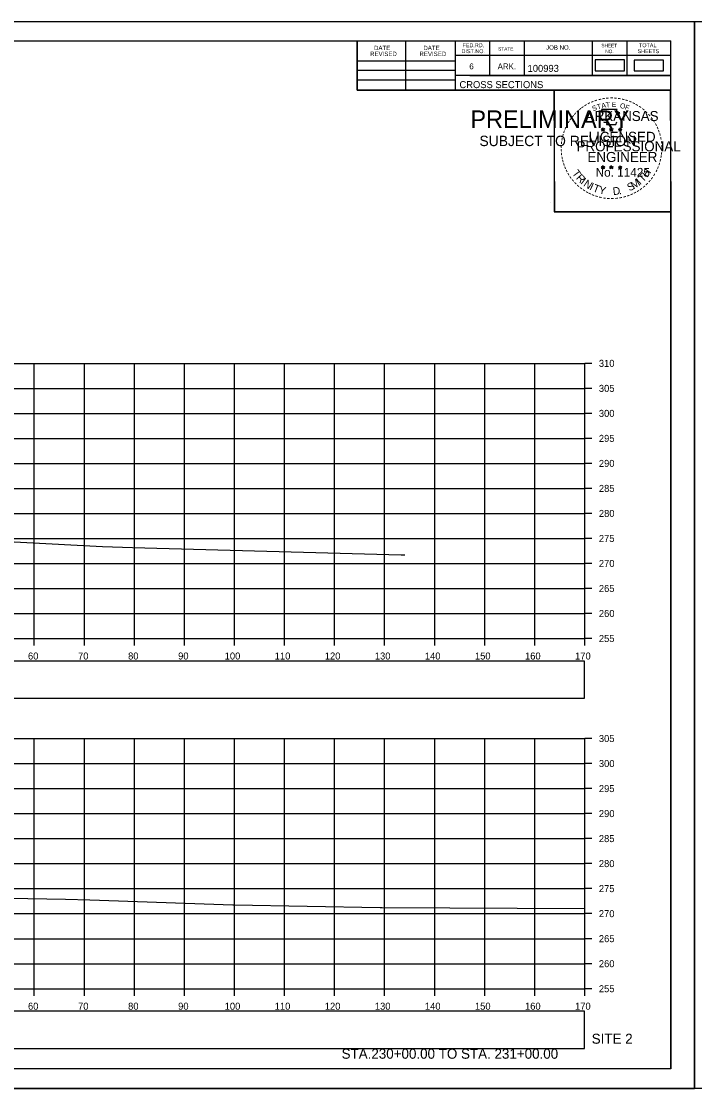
# Model space of a CAD drawing. Extents: x 4667 to 1632277, y -2100 to 724501.
# Drawn here: x 5834.6 to 5969.1, y 596.3 to 809.6 of the extents above; entities that cross this region are included whole.
import ezdxf

# ---------------------------------------------------------------- set-up
doc = ezdxf.new("R2010")
doc.units = 0
for name, color, linetype in [('Default', 7, 'Continuous'), ('R_Axis', 7, 'Continuous'), ('R_Axis Annot', 7, 'Continuous'), ('R_Border', 7, 'Continuous'), ('R_Border PE', 7, 'Continuous'), ('R_Border Prem', 7, 'Continuous'), ('R_Draft', 7, 'Continuous'), ('R_Exist Surface', 7, 'Continuous'), ('R_Grid', 7, 'Continuous'), ('R_No Plot', 7, 'Continuous'), ('R_Proposed CofA', 7, 'Continuous')]:
    doc.layers.add(name, color=color, linetype=linetype)

msp = doc.modelspace()

# ---------------------------------------------------------------- linework, layer by layer
at = {"layer": 'Default'}
for points in [[(5949.24, 799.74), (5955.07, 799.74), (5955.07, 801.92), (5949.24, 801.92)], [(5957.04, 799.71), (5962.87, 799.71), (5962.87, 801.89), (5957.04, 801.89)]]:
    msp.add_lwpolyline(points, close=True, dxfattribs=at)
at = {"layer": 'R_Axis'}
for p, q in [((5947.18, 686.27), (5947.18, 741.27)), ((5948.58, 741.27), (5947.18, 741.27)), ((5948.58, 736.27), (5947.18, 736.27)), ((5948.58, 731.27), (5947.18, 731.27)), ((5948.58, 726.27), (5947.18, 726.27)), ((5948.58, 721.27), (5947.18, 721.27)), ((5948.58, 716.27), (5947.18, 716.27)), ((5948.58, 711.27), (5947.18, 711.27)), ((5948.58, 706.27), (5947.18, 706.27)), ((5948.58, 701.27), (5947.18, 701.27)), ((5948.58, 696.27), (5947.18, 696.27)), ((5948.58, 691.27), (5947.18, 691.27)), ((5667.18, 686.27), (5947.18, 686.27)), ((5837.18, 684.87), (5837.18, 686.27)), ((5847.18, 684.87), (5847.18, 686.27)), ((5857.18, 684.87), (5857.18, 686.27)), ((5867.18, 684.87), (5867.18, 686.27)), ((5877.18, 684.87), (5877.18, 686.27)), ((5887.18, 684.87), (5887.18, 686.27)), ((5897.18, 684.87), (5897.18, 686.27)), ((5907.18, 684.87), (5907.18, 686.27)), ((5917.18, 684.87), (5917.18, 686.27)), ((5927.18, 684.87), (5927.18, 686.27)), ((5937.18, 684.87), (5937.18, 686.27)), ((5947.18, 684.87), (5947.18, 686.27)), ((5948.58, 686.27), (5947.18, 686.27)), ((5947.18, 616.27), (5947.18, 666.27)), ((5948.58, 666.27), (5947.18, 666.27)), ((5948.58, 661.27), (5947.18, 661.27)), ((5948.58, 656.27), (5947.18, 656.27)), ((5948.58, 651.27), (5947.18, 651.27)), ((5948.58, 646.27), (5947.18, 646.27)), ((5948.58, 641.27), (5947.18, 641.27)), ((5948.58, 636.27), (5947.18, 636.27)), ((5948.58, 631.27), (5947.18, 631.27)), ((5948.58, 626.27), (5947.18, 626.27)), ((5948.58, 621.27), (5947.18, 621.27)), ((5667.18, 616.27), (5947.18, 616.27)), ((5837.18, 614.87), (5837.18, 616.27)), ((5847.18, 614.87), (5847.18, 616.27)), ((5857.18, 614.87), (5857.18, 616.27)), ((5867.18, 614.87), (5867.18, 616.27)), ((5877.18, 614.87), (5877.18, 616.27)), ((5887.18, 614.87), (5887.18, 616.27)), ((5897.18, 614.87), (5897.18, 616.27)), ((5907.18, 614.87), (5907.18, 616.27)), ((5917.18, 614.87), (5917.18, 616.27)), ((5927.18, 614.87), (5927.18, 616.27)), ((5937.18, 614.87), (5937.18, 616.27)), ((5947.18, 614.87), (5947.18, 616.27)), ((5948.58, 616.27), (5947.18, 616.27))]:
    msp.add_line(p, q, dxfattribs=at)
at = {"layer": 'R_Border'}
for p, q in [((5648.18, 805.73), (5964.36, 805.73)), ((5901.72, 795.85), (5901.72, 805.73)), ((5911.4, 795.85), (5911.4, 805.73)), ((5921.26, 805.73), (5921.26, 795.85)), ((5928.1, 805.73), (5928.1, 798.79)), ((5935.04, 805.73), (5935.04, 798.79)), ((5948.62, 805.73), (5948.62, 798.79)), ((5955.56, 805.73), (5955.56, 798.79)), ((5964.36, 600.27), (5964.36, 805.73)), ((5964.36, 802.79), (5921.26, 802.79)), ((5964.36, 802.81), (5964.36, 802.81)), ((5901.72, 801.71), (5921.26, 801.71)), ((5901.72, 799.85), (5921.26, 799.85)), ((5901.72, 797.91), (5921.26, 797.91)), ((5964.36, 798.79), (5921.26, 798.79)), ((5924.22, 798.79), (5964.36, 798.79)), ((5964.36, 795.85), (5901.72, 795.85)), ((5964.36, 600.27), (5648.18, 600.27))]:
    msp.add_line(p, q, dxfattribs=at)
at = {"layer": 'R_Border PE'}
for p, q in [((5950.45, 788.11), (5950.8, 788)), ((5950.45, 788.11), (5950.7, 788.06)), ((5950.45, 788.11), (5950.69, 787.99)), ((5950.58, 787.7), (5950.8, 788)), ((5950.58, 787.7), (5950.71, 787.94)), ((5950.58, 787.7), (5950.8, 787.92)), ((5950.8, 788.36), (5950.76, 788.11)), ((5950.8, 788), (5950.8, 788.36)), ((5950.8, 788.36), (5950.85, 788.11)), ((5951.15, 788.11), (5950.8, 788)), ((5951.01, 787.7), (5950.8, 788)), ((5951.01, 787.7), (5950.8, 787.91)), ((5951.15, 788.11), (5950.86, 788.06)), ((5951.01, 787.7), (5950.87, 787.99)), ((5951.15, 788.11), (5950.94, 788.01)), ((5952.12, 788.11), (5952.47, 788)), ((5952.12, 788.11), (5952.37, 788.06)), ((5952.12, 788.11), (5952.36, 787.99)), ((5952.25, 787.7), (5952.47, 788)), ((5952.25, 787.7), (5952.38, 787.94)), ((5952.25, 787.7), (5952.47, 787.92)), ((5952.47, 788.36), (5952.43, 788.11)), ((5952.47, 788), (5952.47, 788.36)), ((5952.47, 788.36), (5952.52, 788.11)), ((5952.82, 788.11), (5952.47, 788)), ((5952.68, 787.7), (5952.47, 788)), ((5952.68, 787.7), (5952.47, 787.91)), ((5952.82, 788.11), (5952.53, 788.06)), ((5952.68, 787.7), (5952.54, 787.99)), ((5952.82, 788.11), (5952.61, 788.01)), ((5953.88, 788.1), (5954.23, 787.99)), ((5953.88, 788.1), (5954.14, 788.05)), ((5953.88, 788.1), (5954.12, 787.97)), ((5954.02, 787.69), (5954.23, 787.99)), ((5954.02, 787.69), (5954.14, 787.93)), ((5954.02, 787.69), (5954.23, 787.91)), ((5954.23, 788.35), (5954.19, 788.1)), ((5954.23, 787.99), (5954.23, 788.35)), ((5954.23, 788.35), (5954.28, 788.1)), ((5954.58, 788.1), (5954.23, 787.99)), ((5954.45, 787.69), (5954.23, 787.99)), ((5954.45, 787.69), (5954.23, 787.9)), ((5954.58, 788.1), (5954.29, 788.05)), ((5954.45, 787.69), (5954.31, 787.98)), ((5954.58, 788.1), (5954.38, 787.99)), ((5950.45, 780.54), (5950.79, 780.42)), ((5950.45, 780.54), (5950.7, 780.49)), ((5950.45, 780.54), (5950.68, 780.41)), ((5950.58, 780.13), (5950.79, 780.42)), ((5950.58, 780.13), (5950.7, 780.37)), ((5950.58, 780.13), (5950.79, 780.34)), ((5950.79, 780.79), (5950.75, 780.54)), ((5950.79, 780.42), (5950.79, 780.79)), ((5950.79, 780.79), (5950.84, 780.54)), ((5951.14, 780.54), (5950.79, 780.42)), ((5951.01, 780.13), (5950.79, 780.42)), ((5951.01, 780.13), (5950.79, 780.34)), ((5951.14, 780.54), (5950.86, 780.49)), ((5951.01, 780.13), (5950.87, 780.42)), ((5951.14, 780.54), (5950.94, 780.43)), ((5952.11, 780.54), (5952.46, 780.42)), ((5952.11, 780.54), (5952.37, 780.49)), ((5952.11, 780.54), (5952.35, 780.41)), ((5952.25, 780.13), (5952.46, 780.42)), ((5952.25, 780.13), (5952.37, 780.37)), ((5952.25, 780.13), (5952.46, 780.34)), ((5952.46, 780.79), (5952.42, 780.54)), ((5952.46, 780.42), (5952.46, 780.79)), ((5952.46, 780.79), (5952.51, 780.54)), ((5952.81, 780.54), (5952.46, 780.42)), ((5952.68, 780.13), (5952.46, 780.42)), ((5952.68, 780.13), (5952.46, 780.34)), ((5952.81, 780.54), (5952.52, 780.49)), ((5952.68, 780.13), (5952.54, 780.42)), ((5952.81, 780.54), (5952.61, 780.43)), ((5953.88, 780.53), (5954.23, 780.41)), ((5953.88, 780.53), (5954.13, 780.48)), ((5953.88, 780.53), (5954.12, 780.4)), ((5954.01, 780.12), (5954.23, 780.41)), ((5954.01, 780.12), (5954.14, 780.36)), ((5954.01, 780.12), (5954.23, 780.33)), ((5954.23, 780.78), (5954.19, 780.53)), ((5954.23, 780.41), (5954.23, 780.78)), ((5954.23, 780.78), (5954.28, 780.53)), ((5954.58, 780.53), (5954.23, 780.41)), ((5954.44, 780.12), (5954.23, 780.41)), ((5954.44, 780.12), (5954.23, 780.33)), ((5954.58, 780.53), (5954.29, 780.48)), ((5954.44, 780.12), (5954.31, 780.41)), ((5954.58, 780.53), (5954.37, 780.42))]:
    msp.add_line(p, q, dxfattribs=at)
for points in [[(5950.49, 791.99), (5950.76, 791.16)], [(5954, 791.06), (5954.14, 791.35), (5953.46, 791.32), (5953.61, 791.99), (5950.49, 791.99)], [(5950.98, 789.56), (5950.98, 789.48), (5951.55, 789.46), (5951.49, 788.98), (5953.36, 788.98), (5953.56, 789.52)], [(5950.8, 788.36), (5951.01, 787.7), (5950.45, 788.11), (5951.15, 788.11), (5950.58, 787.7), (5950.8, 788.36)], [(5952.47, 788.36), (5952.68, 787.7), (5952.12, 788.11), (5952.82, 788.11), (5952.25, 787.7), (5952.47, 788.36)], [(5954.23, 788.35), (5954.45, 787.69), (5953.88, 788.1), (5954.58, 788.1), (5954.02, 787.69), (5954.23, 788.35)], [(5950.79, 780.79), (5951.01, 780.13), (5950.45, 780.54), (5951.14, 780.54), (5950.58, 780.13), (5950.79, 780.79)], [(5952.46, 780.79), (5952.68, 780.13), (5952.11, 780.54), (5952.81, 780.54), (5952.25, 780.13), (5952.46, 780.79)], [(5954.23, 780.78), (5954.44, 780.12), (5953.88, 780.53), (5954.58, 780.53), (5954.01, 780.12), (5954.23, 780.78)]]:
    msp.add_lwpolyline(points, dxfattribs=at)
for centre, radius in [((5950.8, 788), 0.172), ((5950.8, 788), 0.145), ((5950.8, 788), 0.116), ((5950.8, 788), 0.0991), ((5950.8, 788), 0.0747), ((5950.8, 788), 0.0495), ((5950.8, 788), 0.0296), ((5952.47, 788), 0.172), ((5952.47, 788), 0.145), ((5952.47, 788), 0.116), ((5952.47, 788), 0.0991), ((5952.47, 788), 0.0747), ((5952.47, 788), 0.0495), ((5952.47, 788), 0.0296), ((5954.23, 787.98), 0.172), ((5954.23, 787.98), 0.145), ((5954.23, 787.98), 0.116), ((5954.23, 787.98), 0.0991), ((5954.23, 787.98), 0.0747), ((5954.23, 787.98), 0.0495), ((5954.23, 787.98), 0.0296), ((5950.79, 780.42), 0.172), ((5950.79, 780.42), 0.145), ((5950.79, 780.42), 0.116), ((5950.79, 780.42), 0.0991), ((5950.79, 780.42), 0.0747), ((5950.79, 780.42), 0.0495), ((5950.79, 780.42), 0.0296), ((5952.46, 780.42), 0.172), ((5952.46, 780.42), 0.145), ((5952.46, 780.42), 0.116), ((5952.46, 780.42), 0.0991), ((5952.46, 780.42), 0.0747), ((5952.46, 780.42), 0.0495), ((5952.46, 780.42), 0.0296), ((5954.23, 780.41), 0.172), ((5954.23, 780.41), 0.145), ((5954.23, 780.41), 0.116), ((5954.23, 780.41), 0.0991), ((5954.23, 780.41), 0.0747), ((5954.23, 780.41), 0.0495), ((5954.23, 780.41), 0.0296)]:
    msp.add_circle(centre, radius, dxfattribs=at)
at = {"layer": 'R_Exist Surface'}
for points in [[(5816.73, 706.49), (5850.8, 704.64), (5856.81, 704.46), (5910.49, 702.99), (5911.23, 702.96)], [(5817.13, 634.66), (5843.4, 634.16), (5848.28, 634.06), (5876.85, 633.04), (5877.11, 633.03), (5906.26, 632.5), (5906.67, 632.49), (5947.18, 632.31)]]:
    msp.add_lwpolyline(points, dxfattribs=at)
at = {"layer": 'R_Grid'}
for p, q in [((5667.18, 741.27), (5947.18, 741.27)), ((5837.18, 686.27), (5837.18, 741.27)), ((5847.18, 686.27), (5847.18, 741.27)), ((5857.18, 686.27), (5857.18, 741.27)), ((5867.18, 686.27), (5867.18, 741.27)), ((5877.18, 686.27), (5877.18, 741.27)), ((5887.18, 686.27), (5887.18, 741.27)), ((5897.18, 686.27), (5897.18, 741.27)), ((5907.18, 686.27), (5907.18, 741.27)), ((5917.18, 686.27), (5917.18, 741.27)), ((5927.18, 686.27), (5927.18, 741.27)), ((5937.18, 686.27), (5937.18, 741.27)), ((5947.18, 686.27), (5947.18, 741.27)), ((5667.18, 736.27), (5947.18, 736.27)), ((5667.18, 731.27), (5947.18, 731.27)), ((5667.18, 726.27), (5947.18, 726.27)), ((5667.18, 721.27), (5947.18, 721.27)), ((5667.18, 716.27), (5947.18, 716.27)), ((5667.18, 711.27), (5947.18, 711.27)), ((5667.18, 706.27), (5947.18, 706.27)), ((5667.18, 701.27), (5947.18, 701.27)), ((5667.18, 696.27), (5947.18, 696.27)), ((5667.18, 691.27), (5947.18, 691.27)), ((5667.18, 686.27), (5947.18, 686.27)), ((5667.18, 666.27), (5947.18, 666.27)), ((5837.18, 616.27), (5837.18, 666.27)), ((5847.18, 616.27), (5847.18, 666.27)), ((5857.18, 616.27), (5857.18, 666.27)), ((5867.18, 616.27), (5867.18, 666.27)), ((5877.18, 616.27), (5877.18, 666.27)), ((5887.18, 616.27), (5887.18, 666.27)), ((5897.18, 616.27), (5897.18, 666.27)), ((5907.18, 616.27), (5907.18, 666.27)), ((5917.18, 616.27), (5917.18, 666.27)), ((5927.18, 616.27), (5927.18, 666.27)), ((5937.18, 616.27), (5937.18, 666.27)), ((5947.18, 616.27), (5947.18, 666.27)), ((5667.18, 661.27), (5947.18, 661.27)), ((5667.18, 656.27), (5947.18, 656.27)), ((5667.18, 651.27), (5947.18, 651.27)), ((5667.18, 646.27), (5947.18, 646.27)), ((5667.18, 641.27), (5947.18, 641.27)), ((5667.18, 636.27), (5947.18, 636.27)), ((5667.18, 631.27), (5947.18, 631.27)), ((5667.18, 626.27), (5947.18, 626.27)), ((5667.18, 621.27), (5947.18, 621.27)), ((5667.18, 616.27), (5947.18, 616.27))]:
    msp.add_line(p, q, dxfattribs=at)
at = {"layer": 'R_No Plot'}
for p, q in [((5635.78, 809.63), (5969.12, 809.63)), ((5940.4, 773.4), (5940.4, 773.4)), ((5635.78, 596.29), (5969.12, 596.29))]:
    msp.add_line(p, q, dxfattribs=at)
for points in [[(5635.78, 809.63), (5969.12, 809.63), (5969.12, 596.29), (5635.78, 596.29)], [(5969.12, 809.63), (6302.46, 809.63), (6302.46, 596.29), (5969.12, 596.29)], [(5882.1, 805.73), (5901.72, 805.73), (5901.72, 795.85), (5917.84, 795.85), (5941.04, 795.85), (5941.04, 771.52), (5964.36, 771.52), (5964.36, 600.27), (5648.18, 600.27), (5648.18, 805.73)], [(5941.04, 795.85), (5964.24, 795.85), (5964.36, 771.52), (5941.16, 771.52)]]:
    msp.add_lwpolyline(points, close=True, dxfattribs=at)
at = {"layer": 'R_Proposed CofA'}
for points in [[(5667.23, 674.33), (5947.13, 674.33), (5947.13, 681.75), (5667.23, 681.75)], [(5667.23, 604.33), (5947.13, 604.33), (5947.13, 611.75), (5667.23, 611.75)]]:
    msp.add_lwpolyline(points, close=True, dxfattribs=at)

# ---------------------------------------------------------------- texts
at = {"layer": 'R_Axis Annot'}
for s, p in [('310', (5949.98, 740.57)), ('305', (5949.98, 735.57)), ('300', (5949.98, 730.57)), ('295', (5949.98, 725.57)), ('290', (5949.98, 720.57)), ('285', (5949.98, 715.57)), ('280', (5949.98, 710.57)), ('275', (5949.98, 705.57)), ('270', (5949.98, 700.57)), ('265', (5949.98, 695.57)), ('260', (5949.98, 690.57)), ('255', (5949.98, 685.57)), ('60', (5835.92, 682.07)), ('70', (5845.92, 682.07)), ('80', (5855.92, 682.07)), ('90', (5865.92, 682.07)), ('100', (5875.22, 682.07)), ('110', (5885.22, 682.07)), ('120', (5895.22, 682.07)), ('130', (5905.22, 682.07)), ('140', (5915.22, 682.07)), ('150', (5925.22, 682.07)), ('160', (5935.22, 682.07)), ('170', (5945.22, 682.07)), ('305', (5949.98, 665.57)), ('300', (5949.98, 660.57)), ('295', (5949.98, 655.57)), ('290', (5949.98, 650.57)), ('285', (5949.98, 645.57)), ('280', (5949.98, 640.57)), ('275', (5949.98, 635.57)), ('270', (5949.98, 630.57)), ('265', (5949.98, 625.57)), ('260', (5949.98, 620.57)), ('255', (5949.98, 615.57)), ('60', (5835.92, 612.07)), ('70', (5845.92, 612.07)), ('80', (5855.92, 612.07)), ('90', (5865.92, 612.07)), ('100', (5875.22, 612.07)), ('110', (5885.22, 612.07)), ('120', (5895.22, 612.07)), ('130', (5905.22, 612.07)), ('140', (5915.22, 612.07)), ('150', (5925.22, 612.07)), ('160', (5935.22, 612.07)), ('170', (5945.22, 612.07))]:
    msp.add_text(s, height=1.4, dxfattribs=at).set_placement(p)
at = {"layer": 'R_Border'}
for s, height, p in [('DATE', 0.879, (5905.06, 803.87)), ('DATE', 0.879, (5914.92, 803.87)), ('FED.RD.', 0.782, (5922.74, 804.45)), ('STATE', 0.684, (5929.86, 803.77)), ('JOB NO.', 0.879, (5939.44, 803.97)), ('SHEET', 0.684, (5950.48, 804.45)), ('TOTAL', 0.782, (5958, 804.45)), ('REVISED', 0.879, (5904.28, 802.69)), ('REVISED', 0.879, (5914.14, 802.69)), ('DIST.NO.', 0.782, (5922.54, 803.27)), ('NO.', 0.684, (5951.26, 803.27)), ('SHEETS', 0.782, (5957.72, 803.27)), ('6', 1.17, (5924.1, 800.05)), ('ARK.', 1.172, (5929.76, 800.05)), ('100993', 1.4, (5935.74, 799.53)), ('CROSS SECTIONS', 1.4, (5922.13, 796.28))]:
    msp.add_text(s, height=height, rotation=360, dxfattribs=at).set_placement(p)
at = {"layer": 'R_Border PE'}
for s, height, rotation, p in [('-', 1.6, 24.3072, (5948.6, 792.84)), ('-', 1.6, 19.1761, (5949.24, 793.11)), ('-', 1.6, 13.6301, (5949.99, 793.35)), ('-', 1.6, 10.2193, (5950.67, 793.52)), ('-', 1.6, 5.8968, (5951.39, 793.63)), ('-', 1.6, 0.1862, (5952.17, 793.7)), ('-', 1.6, 357.743, (5952.89, 793.69)), ('-', 1.6, 352.1617, (5953.63, 793.63)), ('-', 1.6, 347.2049, (5954.35, 793.52)), ('-', 1.6, 342.3362, (5954.99, 793.36)), ('-', 1.6, 337.8551, (5955.72, 793.14)), ('-', 1.6, 42.9622, (5945.89, 790.97)), ('-', 1.6, 38.9507, (5946.32, 791.38)), ('-', 1.6, 36.2317, (5946.8, 791.76)), ('-', 1.6, 34.0636, (5947.37, 792.16)), ('ARKANSAS', 2, 360, (5947.34, 789.7)), ('-', 1.6, 28.7918, (5947.97, 792.53)), ('S', 1, 21.594, (5948.84, 791.66)), ('T', 1, 16.4036, (5949.76, 792)), ('A', 1, 11.2132, (5950.58, 792.25)), ('T', 1, 6.0228, (5951.43, 792.41)), ('E', 1, 0.8323, (5952.54, 792.52)), ('O', 1, 350.4515, (5954.14, 792.31)), ('F', 1, 340.0707, (5955.1, 792.08)), ('-', 1.6, 334.1211, (5956.35, 792.87)), ('-', 1.6, 329.6409, (5956.93, 792.58)), ('-', 1.6, 325.8627, (5957.58, 792.22)), ('-', 1.6, 320.5297, (5958.19, 791.8)), ('-', 1.6, 315.5786, (5958.78, 791.31)), ('-', 1.6, 58.0706, (5944.3, 788.91)), ('-', 1.6, 54.2325, (5944.62, 789.44)), ('-', 1.6, 50.6142, (5945.04, 790)), ('-', 1.6, 48.423, (5945.44, 790.49)), ('-', 1.6, 309.8797, (5959.35, 790.76)), ('-', 1.6, 306.6522, (5959.88, 790.16)), ('-', 1.4, 303.6753, (5960.36, 789.59)), ('-', 1.6, 72.3945, (5943.51, 787.05)), ('-', 1.6, 67.7743, (5943.73, 787.68)), ('-', 1.6, 62.8713, (5943.98, 788.3)), ('LICENSED', 2, 360, (5947.94, 785.55)), ('DWB', 0.01, 360, (5950.79, 787.99)), ('DWB', 0.01, 360, (5952.46, 787.99)), ('DWB', 0.01, 360, (5954.22, 787.98)), ('-', 1.6, 299.6684, (5960.68, 788.98)), ('-', 1.6, 294.6628, (5961.01, 788.37)), ('-', 1.6, 290.5728, (5961.26, 787.79)), ('-', 1.6, 285.1233, (5961.5, 787.21)), ('-', 1.6, 85.1863, (5943.1, 784.94)), ('-', 1.6, 81.2013, (5943.18, 785.63)), ('-', 1.6, 75.461, (5943.31, 786.34)), ('PROFESSIONAL', 2, 360, (5945.52, 783.65)), ('-', 1.6, 280.5493, (5961.7, 786.47)), ('-', 1.6, 276.5962, (5961.86, 785.7)), ('-', 1.6, 94.1959, (5943.11, 783.51)), ('-', 1.6, 89.0622, (5943.08, 784.24)), ('-', 1.6, 98.9479, (5943.18, 782.84)), ('ENGINEER', 2, 360, (5947.7, 781.52)), ('-', 1.6, 263.5172, (5961.94, 783.68)), ('-', 1.6, 274.3301, (5961.92, 784.98)), ('-', 1.6, 269.9407, (5961.95, 784.35)), ('-', 1.6, 101.7149, (5943.32, 782.11)), ('-', 1.6, 105.4578, (5943.48, 781.52)), ('-', 1.6, 109.0874, (5943.7, 780.88)), ('-', 1.6, 252.8681, (5961.57, 781.63)), ('-', 1.6, 255.7626, (5961.75, 782.35)), ('-', 1.6, 260.9953, (5961.86, 783.03)), ('-', 1.6, 114.0643, (5943.95, 780.29)), ('-', 1.6, 115.7289, (5944.25, 779.67)), ('-', 1.6, 120.4471, (5944.61, 779.08)), ('-', 1.6, 125.8934, (5945.01, 778.52)), ('T', 1.54, 306.0406, (5944.55, 779.26)), ('R', 1.54, 314.005, (5945.32, 778.22)), ('No. 11425', 1.757, 360, (5949.33, 778.57)), ('DWB', 0.01, 360, (5950.78, 780.42)), ('DWB', 0.01, 360, (5952.45, 780.42)), ('DWB', 0.01, 360, (5954.22, 780.41)), ('T', 1.54, 46.6444, (5958.78, 777.36)), ('H', 1.54, 54.6088, (5959.67, 778.3)), ('-', 1.6, 239.0712, (5960.69, 779.58)), ('-', 1.6, 244.6197, (5961.09, 780.33)), ('-', 1.6, 247.8887, (5961.35, 780.96)), ('-', 1.6, 130.7181, (5945.48, 777.97)), ('-', 1.6, 134.2238, (5945.99, 777.43)), ('-', 1.6, 138.9338, (5946.52, 776.96)), ('I', 1.54, 321.9694, (5946.22, 777.28)), ('N', 1.54, 326.5002, (5946.78, 776.81)), ('I', 1.54, 335.3603, (5947.99, 776.03)), ('T', 1.54, 339.8912, (5948.65, 775.7)), ('Y', 1.54, 347.8556, (5949.87, 775.25)), ('S', 1.54, 26.9312, (5956.1, 775.62)), ('M', 1.54, 32.6563, (5956.94, 776.03)), ('I', 1.54, 42.1136, (5958.22, 776.88)), ('-', 1.6, 221.0851, (5958.86, 777.28)), ('-', 1.6, 225.7653, (5959.38, 777.79)), ('-', 1.6, 231.2538, (5959.86, 778.36)), ('-', 1.6, 233.8452, (5960.29, 778.92)), ('-', 1.6, 144.6463, (5947.07, 776.56)), ('-', 1.6, 148.0898, (5947.64, 776.19)), ('-', 1.6, 151.5704, (5948.21, 775.86)), ('-', 1.6, 154.6002, (5948.74, 775.61)), ('-', 1.6, 158.5612, (5949.36, 775.36)), ('-', 1.6, 162.7983, (5950.05, 775.15)), ('-', 1.6, 167.5555, (5950.76, 774.98)), ('-', 1.6, 173.1155, (5951.53, 774.87)), ('D', 1.54, 6.3969, (5952.85, 774.89)), ('-', 1.6, 191.2858, (5954.57, 775.05)), ('.', 1.54, 13.7642, (5954.05, 775.02)), ('-', 1.6, 195.4743, (5955.3, 775.25)), ('-', 1.6, 200.7184, (5955.98, 775.49)), ('-', 1.6, 204.2516, (5956.6, 775.76)), ('-', 1.6, 207.3568, (5957.22, 776.08)), ('-', 1.6, 212.2491, (5957.78, 776.43)), ('-', 1.6, 215.7363, (5958.31, 776.81)), ('-', 1.6, 176.5183, (5952.28, 774.82)), ('-', 1.6, 181.5918, (5953.03, 774.84)), ('-', 1.6, 185.8167, (5953.84, 774.91))]:
    msp.add_text(s, height=height, rotation=rotation, dxfattribs=at).set_placement(p)
at = {"layer": 'R_Border Prem'}
for s, height, p in [('PRELIMINARY', 3.5, (5924.32, 788.32)), ('DWB', 0.01, (5925.06, 790.17)), ('SUBJECT TO REVISION', 2.0751, (5926.12, 784.69))]:
    msp.add_text(s, height=height, rotation=360, dxfattribs=at).set_placement(p)
at = {"layer": 'R_Draft'}
for s, p in [('SITE 2', (5948.55, 605.27)), ('STA.230+00.00 TO STA. 231+00.00', (5898.58, 602.27))]:
    msp.add_text(s, height=2, dxfattribs=at).set_placement(p)

doc.saveas('drawing.dxf')
